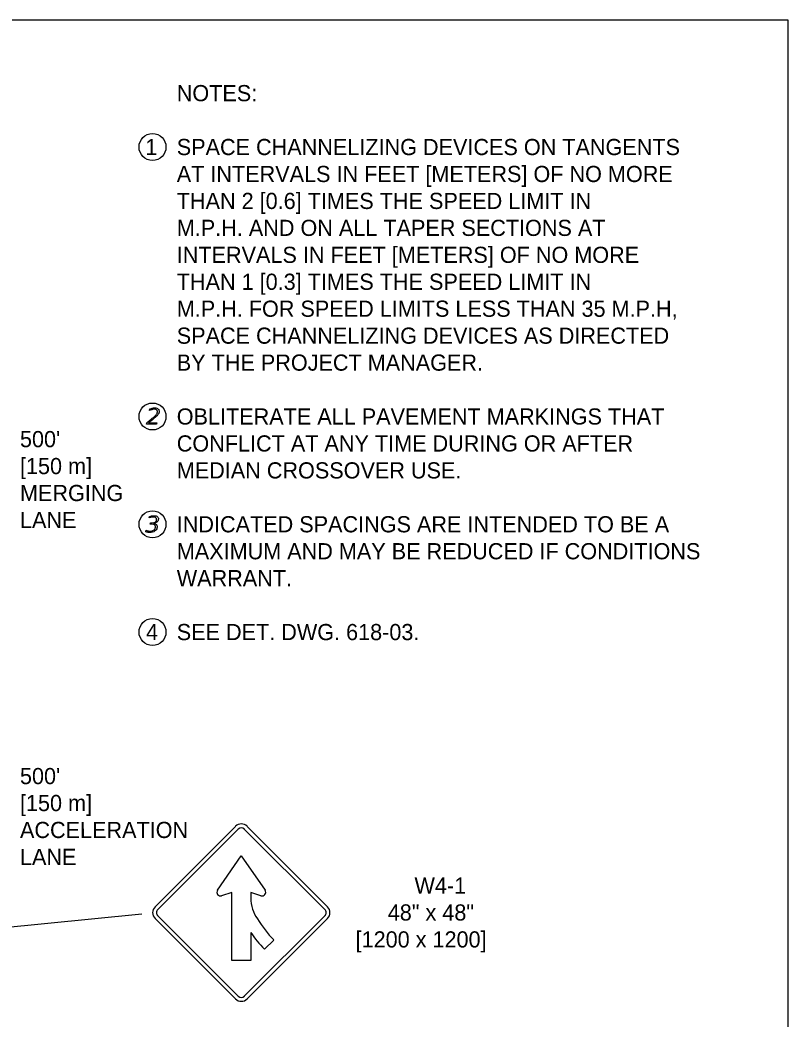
# Model space of a CAD drawing. Extents: x 49991.4 to 50021, y 49987.6 to 50011.4.
# Drawn here: x 50005.764 to 50008.615, y 50007.552 to 50011.263 of the extents above; entities that cross this region are included whole.
import ezdxf

# ---------------------------------------------------------------- set-up
doc = ezdxf.new("R2010")
doc.units = 0
for name, color, linetype in [('Level 1', 7, 'Continuous'), ('Level 2', 7, 'Continuous'), ('Level 3', 7, 'Continuous')]:
    doc.layers.add(name, color=color, linetype=linetype)

msp = doc.modelspace()

# ---------------------------------------------------------------- linework, layer by layer
at = {"layer": 'Level 1'}
for p, q in [((50006.5639, 50008.2704), (50006.265, 50007.9715)), ((50006.5639, 50008.2704), (50006.5639, 50008.2704)), ((50006.9055, 50007.9715), (50006.6066, 50008.2704)), ((50006.5739, 50008.2603), (50006.275, 50007.9614)), ((50006.5739, 50008.2603), (50006.5739, 50008.2603)), ((50006.8953, 50007.9614), (50006.5965, 50008.2603)), ((50006.497, 50008.0332), (50006.5852, 50008.1614)), ((50006.5852, 50008.1614), (50006.6734, 50008.0332)), ((50006.55, 50008.0251), (50006.5122, 50008.0128)), ((50006.55, 50007.7723), (50006.55, 50008.0251)), ((50006.6582, 50008.0128), (50006.6203, 50008.0251)), ((50006.6203, 50008.0251), (50006.6204, 50008.0038)), ((50006.265, 50007.9287), (50006.5639, 50007.6298)), ((50006.275, 50007.9389), (50006.5739, 50007.64)), ((50006.5965, 50007.64), (50006.8953, 50007.9389)), ((50006.6066, 50007.6298), (50006.9055, 50007.9287)), ((50006.6204, 50007.8765), (50006.6204, 50007.7723)), ((50006.7055, 50007.8486), (50006.6711, 50007.8142)), ((50006.6204, 50007.7723), (50006.55, 50007.7723))]:
    msp.add_line(p, q, dxfattribs=at)
msp.add_lwpolyline([(50008.6146, 50011.2628), (50000.3356, 50011.2628), (50000.3356, 50000.0624), (50008.6146, 50000.0624)], close=True, dxfattribs=at)
msp.add_lwpolyline([(50006.5848, 50008.1608), (50006.5853, 50008.1613)], dxfattribs=at)
for centre, radius, start, end in [((50006.5853, 50008.2491), 0.0302, 45.0001, 134.9999), ((50006.5853, 50008.2491), 0.0159, 45.0001, 134.9999), ((50006.5081, 50008.0257), 0.0134, 145.4806, 287.9582), ((50006.7496, 50008.0039), 0.1292, 180, 216.3165), ((50006.6624, 50008.0257), 0.0134, 252.0418, 34.5194), ((50006.2864, 50007.9502), 0.0302, 134.9999, 225.0001), ((50006.8842, 50007.9502), 0.0302, 314.9999, 45.0001), ((50006.2864, 50007.9502), 0.0159, 134.9999, 225.0001), ((50006.8842, 50007.9502), 0.0159, 314.9999, 45.0001), ((50007.0323, 50008.1599), 0.4512, 211.0143, 223.6035), ((50007.0323, 50008.1599), 0.4999, 214.5303, 223.7394), ((50006.5853, 50007.6513), 0.0159, 225.0001, 314.9999), ((50006.5853, 50007.6513), 0.0302, 225.0001, 314.9999)]:
    msp.add_arc(centre, radius, start, end, dxfattribs=at)
at = {"layer": 'Level 2'}
for points in [[(50006.2449, 50009.8135), (50006.2461, 50009.8194)], [(50006.2412, 50009.7673), (50006.2719, 50009.7673), (50006.2708, 50009.7623), (50006.2336, 50009.7623), (50006.2348, 50009.7679)], [(50006.2434, 50009.4155), (50006.2444, 50009.4207)], [(50006.2533, 50009.3918), (50006.2471, 50009.3918), (50006.2482, 50009.3967), (50006.2547, 50009.3967)], [(50006.2305, 50009.3638), (50006.2317, 50009.3693)]]:
    msp.add_lwpolyline(points, dxfattribs=at)
for centre in [(50006.2557, 50010.7914), (50006.2557, 50009.7914), (50006.2557, 50009.3914), (50006.2557, 50008.9914)]:
    msp.add_circle(centre, 0.05, dxfattribs=at)
for points in [[(50006.2461, 50009.8194), (50006.2509, 50009.8212), (50006.2554, 50009.8222), (50006.2599, 50009.8232), (50006.2634, 50009.8232), (50006.2727, 50009.8232), (50006.2771, 50009.8187), (50006.2803, 50009.8153), (50006.2803, 50009.8104), (50006.2803, 50009.8086), (50006.2799, 50009.8066), (50006.2791, 50009.803), (50006.2771, 50009.7997), (50006.275, 50009.7965), (50006.2704, 50009.792), (50006.2692, 50009.7908), (50006.2624, 50009.7851), (50006.2556, 50009.7793), (50006.2412, 50009.7673)], [(50006.2348, 50009.7679), (50006.2403, 50009.7725), (50006.2502, 50009.7808), (50006.2602, 50009.7891), (50006.2629, 50009.7916), (50006.268, 50009.7962), (50006.2704, 50009.7995), (50006.2727, 50009.8028), (50006.2734, 50009.806), (50006.2737, 50009.8075), (50006.2737, 50009.8088), (50006.2737, 50009.8123), (50006.2715, 50009.8148), (50006.2685, 50009.8182), (50006.2625, 50009.8182), (50006.2584, 50009.8182), (50006.2536, 50009.8168), (50006.2488, 50009.8154), (50006.2449, 50009.8135)], [(50006.2547, 50009.3967), (50006.2612, 50009.3967), (50006.2654, 50009.3994), (50006.2696, 50009.4021), (50006.2707, 50009.4073), (50006.2709, 50009.4086), (50006.2709, 50009.4099), (50006.2709, 50009.4133), (50006.2687, 50009.4153), (50006.2655, 50009.4182), (50006.2589, 50009.4182), (50006.2554, 50009.4182), (50006.2512, 50009.4174), (50006.247, 50009.4166), (50006.2434, 50009.4155)], [(50006.2444, 50009.4207), (50006.2486, 50009.4218), (50006.2529, 50009.4225), (50006.2571, 50009.4231), (50006.2607, 50009.4231), (50006.2699, 50009.4231), (50006.2742, 50009.4191), (50006.2775, 50009.416), (50006.2775, 50009.4114), (50006.2775, 50009.4099), (50006.2771, 50009.4081), (50006.2761, 50009.4034), (50006.2727, 50009.4001), (50006.2693, 50009.3968), (50006.2594, 50009.3945)], [(50006.2594, 50009.3945), (50006.2689, 50009.3923), (50006.2713, 50009.3885), (50006.2728, 50009.386), (50006.2728, 50009.3827), (50006.2728, 50009.3811), (50006.2724, 50009.3792), (50006.2706, 50009.3705), (50006.2636, 50009.3658), (50006.2566, 50009.361), (50006.2454, 50009.361), (50006.2416, 50009.361), (50006.2377, 50009.3618), (50006.2338, 50009.3625), (50006.2305, 50009.3638)], [(50006.2317, 50009.3693), (50006.2335, 50009.3682), (50006.2375, 50009.3671), (50006.2416, 50009.366), (50006.2462, 50009.366), (50006.2544, 50009.366), (50006.2596, 50009.3694), (50006.2648, 50009.3728), (50006.2661, 50009.3792), (50006.2665, 50009.3808), (50006.2665, 50009.3822), (50006.2665, 50009.386), (50006.264, 50009.3885), (50006.2605, 50009.3918), (50006.2533, 50009.3918)]]:
    msp.add_open_spline(points, degree=3, dxfattribs=at)
at = {"layer": 'Level 3'}
msp.add_line((50004.2401, 50007.7482), (50006.2164, 50007.9462), dxfattribs=at)

# ---------------------------------------------------------------- texts
at = {"layer": 'Level 2'}
for s, p in [('NOTES:', (50006.3457, 50010.9614)), ('1', (50006.2292, 50010.7614)), ('SPACE CHANNELIZING DEVICES ON TANGENTS ', (50006.3457, 50010.7614)), ('AT INTERVALS IN FEET [METERS] OF NO MORE ', (50006.3457, 50010.6614)), ('THAN 2 [0.6] TIMES THE SPEED LIMIT IN ', (50006.3457, 50010.5614)), ('M.P.H. AND ON ALL TAPER SECTIONS AT ', (50006.3457, 50010.4614)), ('INTERVALS IN FEET [METERS] OF NO MORE ', (50006.3457, 50010.3614)), ('THAN 1 [0.3] TIMES THE SPEED LIMIT IN ', (50006.3457, 50010.2614)), ('M.P.H. FOR SPEED LIMITS LESS THAN 35 M.P.H, ', (50006.3457, 50010.1614)), ('SPACE CHANNELIZING DEVICES AS DIRECTED ', (50006.3457, 50010.0614)), ('BY THE PROJECT MANAGER.', (50006.3457, 50009.9614)), ('OBLITERATE ALL PAVEMENT MARKINGS THAT ', (50006.3457, 50009.7614)), ('CONFLICT AT ANY TIME DURING OR AFTER  ', (50006.3457, 50009.6614)), ('MEDIAN CROSSOVER USE.', (50006.3457, 50009.5614)), ('INDICATED SPACINGS ARE INTENDED TO BE A ', (50006.3457, 50009.3614)), ('MAXIMUM AND MAY BE REDUCED IF CONDITIONS ', (50006.3457, 50009.2614)), ('WARRANT.', (50006.3457, 50009.1614)), ('4', (50006.2317, 50008.9614)), ('SEE DET. DWG. 618-03. ', (50006.3457, 50008.9614)), ('W4-1', (50007.2282, 50008.0208)), ('48" x 48"', (50007.129, 50007.9208)), ('[1200 x 1200]', (50007.0095, 50007.8208))]:
    msp.add_text(s, height=0.06, dxfattribs=at).set_placement(p)
for s, p in [("500'", (50005.7637, 50009.6774)), ('[150 m]', (50005.7637, 50009.5774)), ('MERGING', (50005.7638, 50009.4774)), ('LANE', (50005.7638, 50009.3774)), ("500'", (50005.7637, 50008.4269)), ('[150 m]', (50005.7637, 50008.3269)), ('ACCELERATION', (50005.7638, 50008.2269)), ('LANE', (50005.7638, 50008.1269))]:
    msp.add_text(s, height=0.06, rotation=0.0174, dxfattribs=at).set_placement(p)

doc.saveas('drawing.dxf')
